// Mitsubishi GX Works2 project: 用模拟量计算当前温度   PLC: FX3U/FX3UC

PROGRAM MAIN
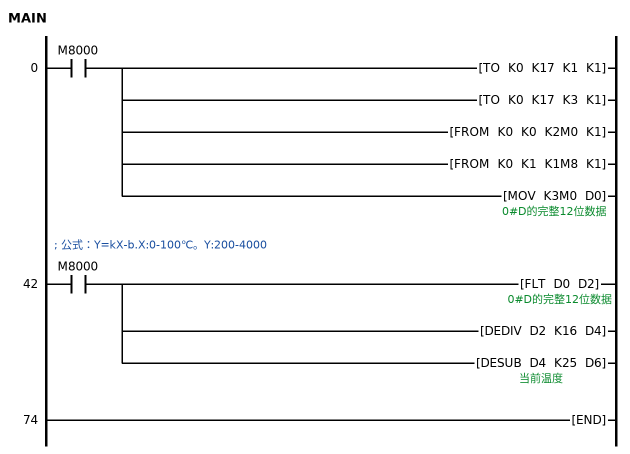
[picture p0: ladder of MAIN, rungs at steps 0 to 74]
0     LD      M8000
      TO      K0 K17 K1 K1
        [note] 写K1到1#A\D模块17号D，选择通道2
      TO      K0 K17 K3 K1
        [note] 写K3到1#A\D模块17号D，启动通道2
      FROM    K0 K0 K2M0 K1  ; 0#D的低8位数据
        [note] 将1#模块的0号D低8位读到K2M0
      FROM    K0 K1 K1M8 K1  ; 0#D的高4位数据
        [note] 将1#模块的0号D高4位读到K2M8
      MOV     K3M0 D0  ; 0#D的完整12位数据
        [note] 把高4位低8位合起来存到D0
; 公式：Y=kX-b.X:0-100℃。Y:200-4000
42    LD      M8000
      FLT     D0 D2
        [note] D0转为浮点数
      DEDIV   D2 K16 D4
        [note] 通过公式计算温度
      DESUB   D4 K25 D6  ; 当前温度
74    END
END_PROGRAM
